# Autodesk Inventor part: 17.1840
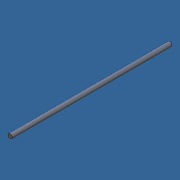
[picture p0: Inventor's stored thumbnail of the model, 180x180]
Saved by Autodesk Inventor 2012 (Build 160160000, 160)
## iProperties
Created: 2007-07
Part Number: 17.1840
Material: Steel
Document SubType Name: Modeling
Designer: Andy Moles
Density: 7.85 g/cm^3
Description: 8mm DIA SHAFT L = SPECIFY +/- 1/32"
Vendor: F
Author: Andy Moles
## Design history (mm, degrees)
sketch "Sketch1"
  geometry: C1 r 4 at (0, 0); 1 further point
  constraints: 1 centre point, 1 coincident
  dimensions: "d0" = 8 diameter of C1
extrude "Extrusion1" new body sketch "Sketch1" stored distance "d1" = 295 (= ROD_LENGTH); taper "d2" = 0 deg
body "Solid1"
other parameters: "ROD_LENGTH" = 295 (computed from FRAME_ID) [user parameter; used in 1 equation term]
